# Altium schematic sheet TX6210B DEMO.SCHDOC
size A; SheetNumber: 0; SheetTotal: 0
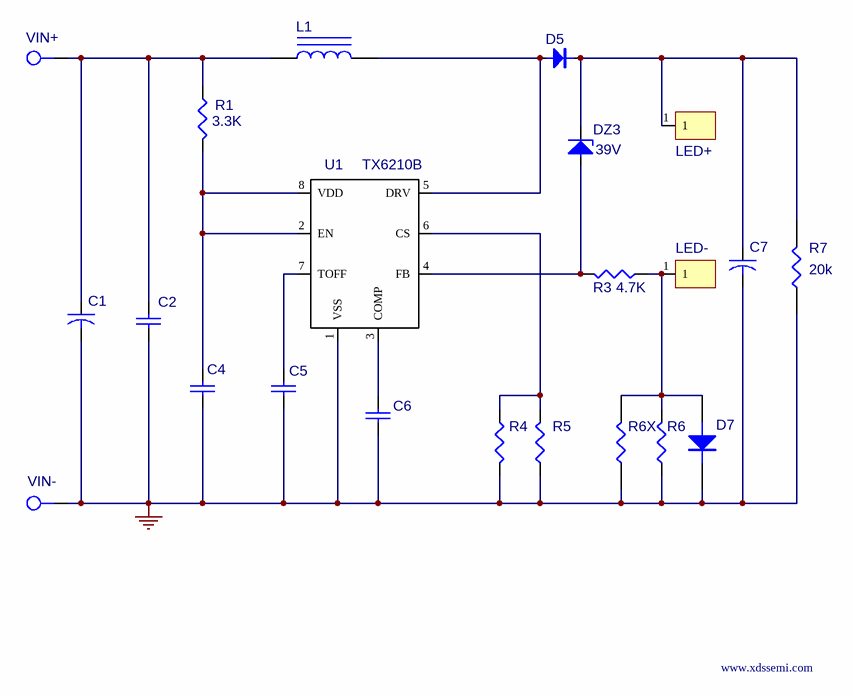
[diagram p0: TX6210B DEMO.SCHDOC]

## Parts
C1  (no value)  [CINJ]
C2  (no value)  [0805]
C4  (no value)  [0805]
C5  (no value)  [0805]
C6  (no value)  [0805]
C7  (no value)  [CINJ]
D5  (no value)  [SMBJ]
D7  (no value)
DZ3  39V  [DZJ]
E  LED+  [OUT]
F  LED-  [OUT]
L1  (no value)  [TJJ]
R1  3.3K  [0805]
R3  4.7K  [0805]
R4  (no value)  [1206]
R5  (no value)  [1206]
R6  (no value)  [0805]
R6X  (no value)
R7  20k
U1  TX6210B  [SO8J]
VIN+  (no value)  [P]
VIN-  (no value)  [P]

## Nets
GND: C1.2 C2.1 C4.1 C5.1 C6.1 C7.2 D7.2(K) R4.2 R5.1 R6.1 R6X.1 R7.1 U1.1(VSS) VIN-.P
NetC1_1: C1.1 C2.2 L1.1 R1.1 VIN+.P
NetC4_2: C4.2 R1.2 U1.2(EN) U1.8(VDD)
NetC5_2: C5.2 U1.7(TOFF)
NetC6_2: C6.2 U1.3(COMP)
NetC7_1: C7.1 D5.2(K) DZ3.2 E.1 R7.2
NetD5_1: D5.1(A) L1.2 U1.5(DRV)
NetD7_1: D7.1(A) F.1 R3.1 R6.2 R6X.2
NetDZ3_1: DZ3.1 R3.2 U1.4(FB)
NetR4_1: R4.1 R5.2 U1.6(CS)

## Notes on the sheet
- www.xdssemi.com

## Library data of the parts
C1 C7 = CAPACITOR
C2 C4-C6 = CAP: Capacitor
D5 D7 = DIODE
DZ3 = ZENER1: Zener Diode
E F = IN
L1 = INDUCTOR IRON
R1 R3-R6 R6X R7 = RES1
U1 = Component_1
VIN+ VIN- = P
